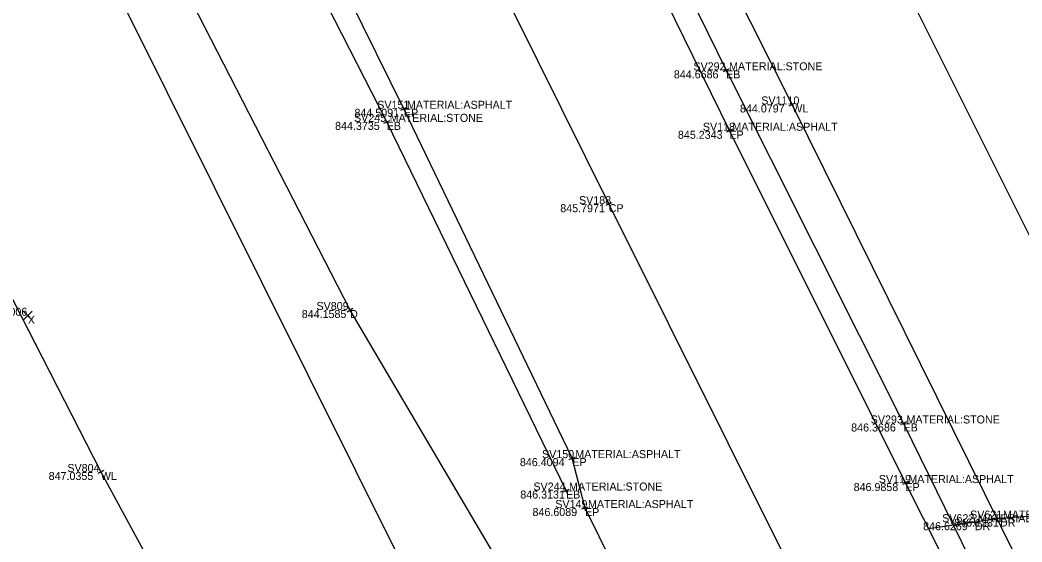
# Model space of a CAD drawing. Extents: x 1715717 to 1717046, y 393954 to 396000.
# Drawn here: x 1716377.5 to 1716452.6, y 394316.6 to 394355.7 of the extents above; entities that cross this region are included whole.
import ezdxf

# ---------------------------------------------------------------- set-up
doc = ezdxf.new("R2010")
doc.units = 0
for name, color, linetype in [('DR_X_Ditch', 7, 'Continuous'), ('PV_X_COP', 7, 'Continuous'), ('PV_X_Driveway', 7, 'Continuous'), ('PV_X_EOP', 7, 'Continuous'), ('PV_X_Shoulder', 7, 'Continuous'), ('SV_X_Random_Point', 7, 'Continuous'), ('SV_X_Shot_Marker', 7, 'Continuous'), ('SV_X_Text_Comment', 7, 'Continuous'), ('SV_X_Text_Description', 7, 'Continuous'), ('SV_X_Text_Elevation', 7, 'Continuous'), ('SV_X_Text_Name', 7, 'Continuous'), ('UT_X_Overhead_Electric', 7, 'Continuous'), ('UT_X_Overhead_Telecom', 7, 'Continuous'), ('UT_X_Water', 7, 'Continuous')]:
    doc.layers.add(name, color=color, linetype=linetype)

msp = doc.modelspace()

# ---------------------------------------------------------------- linework, layer by layer
at = {"layer": 'DR_X_Ditch'}
msp.add_lwpolyline([(1716415.68, 394311.255), (1716402.286, 394333.967), (1716389.986, 394357.959), (1716379.118, 394373.823), (1716366.147, 394395.156), (1716353.455, 394415.716), (1716341.615, 394437.995), (1716329.621, 394455.372), (1716321.718, 394479.127), (1716315.745, 394495.26), (1716304.628, 394514.895), (1716291.095, 394535.863), (1716283.778, 394548.718), (1716269.083, 394579.449), (1716252.09, 394607.64), (1716231.426, 394633.87), (1716225.839, 394642.475), (1716225.385, 394644.391), (1716223.058, 394654.971)], dxfattribs=at)
at = {"layer": 'PV_X_COP'}
msp.add_lwpolyline([(1716316.414, 394551.825), (1716329.976, 394525.067), (1716342.636, 394500.704), (1716355.433, 394474.91), (1716368.061, 394449.349), (1716381.471, 394422.496), (1716394.063, 394396.972), (1716407.481, 394370.484), (1716421.67, 394341.897), (1716435.056, 394315.11), (1716447.598, 394290.073), (1716460.11, 394264.711), (1716472.688, 394239.147), (1716486.084, 394212.497), (1716500.211, 394184.032), (1716512.528, 394158.684), (1716522.867, 394138.689), (1716535.301, 394112.616), (1716550.327, 394081.503)], dxfattribs=at)
at = {"layer": 'PV_X_Driveway'}
msp.add_lwpolyline([(1716496.822, 394331.939), (1716476.923, 394324.685), (1716459.844, 394318.979), (1716451.003, 394318.34), (1716445.645, 394317.565)], dxfattribs=at)
at = {"layer": 'PV_X_EOP'}
for p, q in [((1716406.325, 394349.044), (1716394.275, 394373.328)), ((1716418.945, 394322.87), (1716406.325, 394349.044)), ((1716419.897, 394319.13), (1716418.945, 394322.87)), ((1716424.759, 394309.31), (1716419.897, 394319.13))]:
    msp.add_line(p, q, dxfattribs=at)
msp.add_lwpolyline([(1716325.745, 394558.401), (1716339.307, 394531.886), (1716352.495, 394505.716), (1716365.434, 394479.596), (1716378.649, 394453.375), (1716392.134, 394426.202), (1716405.281, 394399.087), (1716418.421, 394372.491), (1716430.719, 394347.397), (1716443.91, 394321.001), (1716457.061, 394294.961), (1716470.534, 394268.026), (1716482.82, 394243.949), (1716495.604, 394217.898), (1716508.986, 394190.998), (1716522.378, 394163.925), (1716535.043, 394138.114), (1716548.854, 394110.204), (1716560.842, 394086.425)], dxfattribs=at)
at = {"layer": 'PV_X_Shoulder'}
for points in [[(1716418.474, 394320.442), (1716405.031, 394348.065), (1716391.128, 394375.288), (1716377.545, 394402.127), (1716364.916, 394427.407), (1716352.922, 394452.306), (1716340.479, 394476.675), (1716325.242, 394506.534), (1716313.515, 394528.683), (1716299.446, 394557.272), (1716287.172, 394581.095), (1716274.891, 394606.655), (1716262.618, 394630.715), (1716250.754, 394654.847), (1716237.766, 394680.01), (1716227.152, 394700.982), (1716215.234, 394724.013), (1716202.656, 394749.78), (1716192.032, 394770.132)], [(1716326.152, 394561.274), (1716340.202, 394533.806), (1716352.993, 394507.818), (1716366.465, 394482.197), (1716379.274, 394455.431), (1716392.58, 394429.704), (1716405.346, 394404.366), (1716417.24, 394378.921), (1716430.471, 394351.926), (1716443.768, 394325.466), (1716457.401, 394297.648), (1716469.758, 394273.448), (1716482.564, 394247.113), (1716495.517, 394222.32), (1716505.286, 394201.352), (1716519.457, 394171.849)]]:
    msp.add_lwpolyline(points, dxfattribs=at)
at = {"layer": 'SV_X_Random_Point'}
for p, q in [((1716377.794, 394333.204), (1716378.461, 394333.871)), ((1716377.794, 394333.871), (1716378.461, 394333.204))]:
    msp.add_line(p, q, dxfattribs=at)
at = {"layer": 'SV_X_Shot_Marker'}
for p, q in [((1716430.696, 394352.036), (1716430.247, 394351.816)), ((1716430.361, 394352.15), (1716430.581, 394351.701)), ((1716430.471, 394351.926), (1716430.471, 394351.926)), ((1716406.101, 394348.933), (1716406.549, 394349.156)), ((1716406.437, 394348.821), (1716406.214, 394349.268)), ((1716406.325, 394349.044), (1716406.325, 394349.044)), ((1716435.203, 394349.258), (1716435.651, 394349.48)), ((1716435.538, 394349.145), (1716435.316, 394349.593)), ((1716435.427, 394349.369), (1716435.427, 394349.369)), ((1716404.806, 394347.956), (1716405.256, 394348.175)), ((1716405.14, 394347.841), (1716404.921, 394348.29)), ((1716405.031, 394348.065), (1716405.031, 394348.065)), ((1716430.943, 394347.507), (1716430.494, 394347.287)), ((1716430.609, 394347.621), (1716430.829, 394347.172)), ((1716430.719, 394347.397), (1716430.719, 394347.397)), ((1716421.894, 394342.009), (1716421.446, 394341.786)), ((1716421.559, 394342.121), (1716421.781, 394341.674)), ((1716421.67, 394341.897), (1716421.67, 394341.897)), ((1716402.07, 394333.84), (1716402.501, 394334.094)), ((1716402.413, 394333.752), (1716402.159, 394334.183)), ((1716402.286, 394333.967), (1716402.286, 394333.967)), ((1716443.656, 394325.689), (1716443.881, 394325.242)), ((1716443.992, 394325.578), (1716443.545, 394325.353)), ((1716443.768, 394325.466), (1716443.768, 394325.466)), ((1716418.72, 394322.761), (1716419.171, 394322.979)), ((1716419.054, 394322.645), (1716418.837, 394323.095)), ((1716418.945, 394322.87), (1716418.945, 394322.87)), ((1716383.827, 394321.947), (1716383.382, 394321.719)), ((1716383.49, 394322.056), (1716383.718, 394321.611)), ((1716383.604, 394321.833), (1716383.604, 394321.833)), ((1716443.798, 394321.225), (1716444.021, 394320.778)), ((1716418.249, 394320.333), (1716418.699, 394320.552)), ((1716418.583, 394320.217), (1716418.365, 394320.667)), ((1716418.474, 394320.442), (1716418.474, 394320.442)), ((1716444.133, 394321.113), (1716443.686, 394320.89)), ((1716443.91, 394321.001), (1716443.91, 394321.001)), ((1716419.654, 394319.069), (1716420.139, 394319.192)), ((1716419.958, 394318.888), (1716419.835, 394319.373)), ((1716419.897, 394319.13), (1716419.897, 394319.13)), ((1716449.155, 394317.82), (1716449.083, 394318.315)), ((1716451.252, 394318.359), (1716450.753, 394318.322)), ((1716451.021, 394318.091), (1716450.985, 394318.59)), ((1716451.003, 394318.34), (1716451.003, 394318.34)), ((1716449.366, 394318.104), (1716448.871, 394318.032)), ((1716449.119, 394318.068), (1716449.119, 394318.068))]:
    msp.add_line(p, q, dxfattribs=at)
at = {"layer": 'UT_X_Overhead_Electric'}
msp.add_line((1716495.469, 394254.94), (1716355.28, 394535.607), dxfattribs=at)
at = {"layer": 'UT_X_Overhead_Telecom'}
msp.add_line((1716377.83, 394371.807), (1716458.034, 394211.037), dxfattribs=at)
at = {"layer": 'UT_X_Water'}
for points in [[(1716209.422, 394676.603), (1716226.526, 394640.157), (1716246.856, 394599.269), (1716285.844, 394512.956), (1716341.244, 394404.562), (1716383.609, 394321.849), (1716409.424, 394274.269)], [(1716209.432, 394676.557), (1716226.535, 394640.115), (1716246.863, 394599.23), (1716285.847, 394512.924), (1716341.243, 394404.54), (1716383.604, 394321.833), (1716409.417, 394274.258)], [(1716467.938, 394283.698), (1716435.427, 394349.369), (1716377.591, 394464.091)]]:
    msp.add_lwpolyline(points, dxfattribs=at)

# ---------------------------------------------------------------- texts
at = {"layer": 'SV_X_Text_Comment'}
for s, p in [('EB', (1716430.471, 394351.326)), ('EP', (1716406.325, 394348.444)), ('WL', (1716435.427, 394348.769)), ('EB', (1716405.031, 394347.465)), ('EP', (1716430.719, 394346.797)), ('CP', (1716421.67, 394341.297)), ('D', (1716402.286, 394333.367)), ('X', (1716378.127, 394332.938)), ('EB', (1716443.768, 394324.866)), ('EP', (1716418.945, 394322.27)), ('WL', (1716383.604, 394321.233)), ('EB', (1716418.474, 394319.842)), ('EP', (1716443.91, 394320.401)), ('EP', (1716419.897, 394318.53)), ('DR', (1716451.003, 394317.741)), ('DR', (1716449.119, 394317.468))]:
    msp.add_text(s, height=0.6, dxfattribs=at).set_placement(p)
at = {"layer": 'SV_X_Text_Description'}
for s, p in [(' MATERIAL:STONE ', (1716430.471, 394351.926)), (' MATERIAL:ASPHALT ', (1716406.325, 394349.044)), (' MATERIAL:STONE ', (1716405.031, 394348.065)), (' MATERIAL:ASPHALT ', (1716430.719, 394347.397)), (' MATERIAL:STONE ', (1716443.768, 394325.466)), (' MATERIAL:ASPHALT ', (1716418.945, 394322.87)), (' MATERIAL:ASPHALT ', (1716443.91, 394321.001)), (' MATERIAL:STONE ', (1716418.474, 394320.442)), (' MATERIAL:ASPHALT ', (1716419.897, 394319.13)), (' MATERIAL:STONE  TYPE:FIELD ', (1716451.003, 394318.34)), (' MATERIAL:STONE  TYPE:FIELD ', (1716449.119, 394318.068))]:
    msp.add_text(s, height=0.6, dxfattribs=at).set_placement(p)
at = {"layer": 'SV_X_Text_Elevation'}
for s, p in [('844.6686', (1716426.555, 394351.326)), ('844.5091', (1716402.617, 394348.444)), ('844.0797', (1716431.511, 394348.769)), ('844.3735', (1716401.162, 394347.465)), ('845.2343', (1716426.859, 394346.797)), ('845.7971', (1716418.042, 394341.297)), ('844.1585', (1716398.663, 394333.367)), ('846.3686', (1716439.847, 394324.866)), ('846.4094', (1716415.015, 394322.27)), ('847.0355', (1716379.693, 394321.233)), ('846.3131', (1716415.045, 394319.842)), ('846.9858', (1716440.031, 394320.401)), ('846.6089', (1716415.961, 394318.53)), ('846.1331', (1716447.573, 394317.741)), ('846.6269', (1716445.24, 394317.468))]:
    msp.add_text(s, height=0.6, dxfattribs=at).set_placement(p)
at = {"layer": 'SV_X_Text_Name'}
for s, p in [('SV292', (1716428.02, 394351.926)), ('SV1110', (1716433.109, 394349.369)), ('SV151', (1716404.323, 394349.044)), ('SV245', (1716402.579, 394348.065)), ('SV118', (1716428.731, 394347.397)), ('SV188', (1716419.445, 394341.897)), ('SV1006', (1716375.237, 394333.537)), ('SV809', (1716399.768, 394333.967)), ('SV293', (1716441.312, 394325.466)), ('SV150', (1716416.673, 394322.87)), ('SV804', (1716381.096, 394321.833)), ('SV119', (1716441.921, 394321.001)), ('SV244', (1716416.027, 394320.442)), ('SV149', (1716417.667, 394319.13)), ('SV621', (1716448.764, 394318.34)), ('SV622', (1716446.667, 394318.068))]:
    msp.add_text(s, height=0.6, dxfattribs=at).set_placement(p)

doc.saveas('drawing.dxf')
